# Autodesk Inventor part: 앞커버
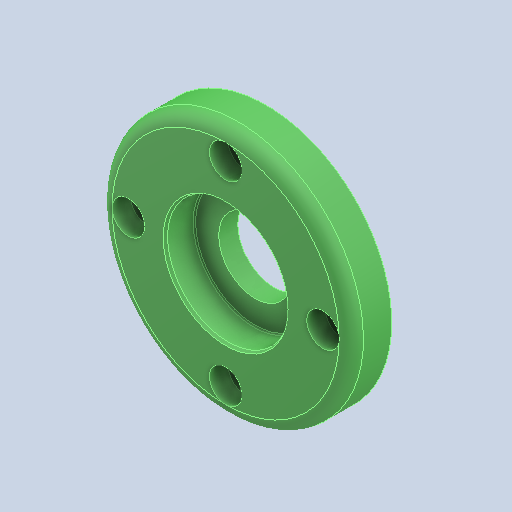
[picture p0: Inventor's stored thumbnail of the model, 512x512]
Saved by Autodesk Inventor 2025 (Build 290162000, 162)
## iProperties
Created: 2024-07
Part Number: 앞커버
Material: 알루미늄 6061
Document SubType Name: Modeling
Designer: myung
Density: 2.71 g/cm^3
Appearance: 기본값
Author: jhkim
Sending System: Autodesk Inventor 2025
Preprocessor: ST-DEVELOPER v20
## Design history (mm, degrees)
feature "솔리드1"
node "솔리드2"
